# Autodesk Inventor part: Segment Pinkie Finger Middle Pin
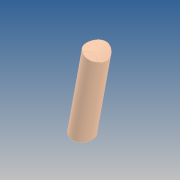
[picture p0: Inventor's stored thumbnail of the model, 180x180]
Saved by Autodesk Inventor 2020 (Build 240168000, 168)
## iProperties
Created: 2019-10
Part Number: Segment Pinkie Finger Middle Pin
Material: GFRP
Document SubType Name: Modeling
Designer: yello
Density: 1.75 g/cm^3
Appearance: Default
Author: yello
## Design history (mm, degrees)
feature "Paliczek MA"
sketch "Sketch1"
  geometry: C1 r 2 at (0, 0); C2 r 33.488 at (6.35, 1.587); 1 further point
  constraints: 2 centre point
  dimensions: "d0" = 4 diameter of C1
extrude "Extrusion1" cut sketch "Sketch1" stored distance "d1" = 100; taper "d2" = 0 deg
loft "Loft1" dims "d3" = 0, "d4" = 90 deg, "d5" = 0, "d6" = 90 deg
  node "Edges1"
  node "Edges2"
body "Solid1"
